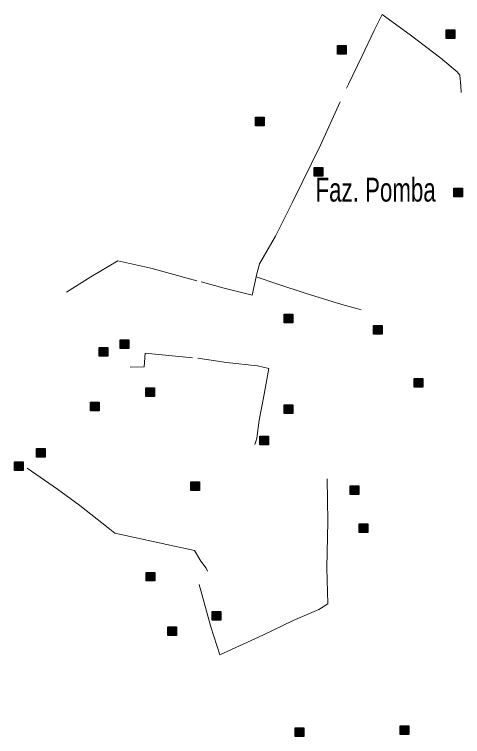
# Model space of a CAD drawing. Extents: x 445.6 to 500, y 8618.1 to 8673.4.
# Drawn here: x 450.664 to 453.675, y 8662.032 to 8666.886 of the extents above; entities that cross this region are included whole.
import ezdxf

# ---------------------------------------------------------------- set-up
doc = ezdxf.new("R2010")
doc.units = 0
doc.header["$LTSCALE"] = 0.064
doc.linetypes.add('DOT_DASHED', pattern=[7.7, 5, -1.2, 0.3, -1.2])
doc.layers.add('2', color=7, linetype='Continuous', lineweight=25)
doc.layers.add('22', color=7, linetype='DOT_DASHED', lineweight=13)
doc.layers.add('61', color=7, linetype='Continuous')

msp = doc.modelspace()

# ---------------------------------------------------------------- hatches: boundary and pattern name
at = {"layer": '2'}
for points in [[(453.5643, 8666.783), (453.6223, 8666.783), (453.6223, 8666.725), (453.5643, 8666.725)], [(452.8348, 8666.6766), (452.8928, 8666.6766), (452.8928, 8666.6186), (452.8348, 8666.6186)], [(452.2843, 8666.1955), (452.3423, 8666.1955), (452.3423, 8666.1375), (452.2843, 8666.1375)], [(452.678, 8665.8576), (452.736, 8665.8576), (452.736, 8665.7996), (452.678, 8665.7996)], [(453.6167, 8665.719), (453.6747, 8665.719), (453.6747, 8665.661), (453.6167, 8665.661)], [(452.4762, 8664.8717), (452.5342, 8664.8717), (452.5342, 8664.8137), (452.4762, 8664.8137)], [(453.0763, 8664.7941), (453.1343, 8664.7941), (453.1343, 8664.7361), (453.0763, 8664.7361)], [(451.3756, 8664.6985), (451.4336, 8664.6985), (451.4336, 8664.6405), (451.3756, 8664.6405)], [(451.2337, 8664.6477), (451.2917, 8664.6477), (451.2917, 8664.5897), (451.2337, 8664.5897)], [(453.3499, 8664.4384), (453.4079, 8664.4384), (453.4079, 8664.3804), (453.3499, 8664.3804)], [(451.5478, 8664.3769), (451.6058, 8664.3769), (451.6058, 8664.3189), (451.5478, 8664.3189)], [(451.1762, 8664.2792), (451.2342, 8664.2792), (451.2342, 8664.2212), (451.1762, 8664.2212)], [(452.4762, 8664.2619), (452.5342, 8664.2619), (452.5342, 8664.2039), (452.4762, 8664.2039)], [(452.3131, 8664.0514), (452.3711, 8664.0514), (452.3711, 8663.9934), (452.3131, 8663.9934)], [(450.8132, 8663.9672), (450.8712, 8663.9672), (450.8712, 8663.9092), (450.8132, 8663.9092)], [(450.6645, 8663.8791), (450.7225, 8663.8791), (450.7225, 8663.8211), (450.6645, 8663.8211)], [(451.8485, 8663.7436), (451.9065, 8663.7436), (451.9065, 8663.6856), (451.8485, 8663.6856)], [(452.9192, 8663.7165), (452.9772, 8663.7165), (452.9772, 8663.6585), (452.9192, 8663.6585)], [(452.98, 8663.4624), (453.038, 8663.4624), (453.038, 8663.4044), (452.98, 8663.4044)], [(451.5487, 8663.1358), (451.6067, 8663.1358), (451.6067, 8663.0778), (451.5487, 8663.0778)], [(451.9921, 8662.8724), (452.0501, 8662.8724), (452.0501, 8662.8144), (451.9921, 8662.8144)], [(451.6953, 8662.7697), (451.7533, 8662.7697), (451.7533, 8662.7117), (451.6953, 8662.7117)], [(452.5499, 8662.0899), (452.6079, 8662.0899), (452.6079, 8662.0319), (452.5499, 8662.0319)], [(453.2558, 8662.1034), (453.3138, 8662.1034), (453.3138, 8662.0454), (453.2558, 8662.0454)]]:
    msp.add_hatch(color=256, dxfattribs=at).paths.add_polyline_path(points)

# ---------------------------------------------------------------- linework, layer by layer
for points in [[(453.5643, 8666.783), (453.6223, 8666.783), (453.6223, 8666.725), (453.5643, 8666.725)], [(452.8348, 8666.6766), (452.8928, 8666.6766), (452.8928, 8666.6186), (452.8348, 8666.6186)], [(452.2843, 8666.1955), (452.3423, 8666.1955), (452.3423, 8666.1375), (452.2843, 8666.1375)], [(452.678, 8665.8576), (452.736, 8665.8576), (452.736, 8665.7996), (452.678, 8665.7996)], [(453.6167, 8665.719), (453.6747, 8665.719), (453.6747, 8665.661), (453.6167, 8665.661)], [(452.4762, 8664.8717), (452.5342, 8664.8717), (452.5342, 8664.8137), (452.4762, 8664.8137)], [(453.0763, 8664.7941), (453.1343, 8664.7941), (453.1343, 8664.7361), (453.0763, 8664.7361)], [(451.3756, 8664.6985), (451.4336, 8664.6985), (451.4336, 8664.6405), (451.3756, 8664.6405)], [(451.2337, 8664.6477), (451.2917, 8664.6477), (451.2917, 8664.5897), (451.2337, 8664.5897)], [(453.3499, 8664.4384), (453.4079, 8664.4384), (453.4079, 8664.3804), (453.3499, 8664.3804)], [(451.5478, 8664.3769), (451.6058, 8664.3769), (451.6058, 8664.3189), (451.5478, 8664.3189)], [(451.1762, 8664.2792), (451.2342, 8664.2792), (451.2342, 8664.2212), (451.1762, 8664.2212)], [(452.4762, 8664.2619), (452.5342, 8664.2619), (452.5342, 8664.2039), (452.4762, 8664.2039)], [(452.3131, 8664.0514), (452.3711, 8664.0514), (452.3711, 8663.9934), (452.3131, 8663.9934)], [(450.8132, 8663.9672), (450.8712, 8663.9672), (450.8712, 8663.9092), (450.8132, 8663.9092)], [(450.6645, 8663.8791), (450.7225, 8663.8791), (450.7225, 8663.8211), (450.6645, 8663.8211)], [(451.8485, 8663.7436), (451.9065, 8663.7436), (451.9065, 8663.6856), (451.8485, 8663.6856)], [(452.9192, 8663.7165), (452.9772, 8663.7165), (452.9772, 8663.6585), (452.9192, 8663.6585)], [(452.98, 8663.4624), (453.038, 8663.4624), (453.038, 8663.4044), (452.98, 8663.4044)], [(451.5487, 8663.1358), (451.6067, 8663.1358), (451.6067, 8663.0778), (451.5487, 8663.0778)], [(451.9921, 8662.8724), (452.0501, 8662.8724), (452.0501, 8662.8144), (451.9921, 8662.8144)], [(451.6953, 8662.7697), (451.7533, 8662.7697), (451.7533, 8662.7117), (451.6953, 8662.7117)], [(452.5499, 8662.0899), (452.6079, 8662.0899), (452.6079, 8662.0319), (452.5499, 8662.0319)], [(453.2558, 8662.1034), (453.3138, 8662.1034), (453.3138, 8662.0454), (453.2558, 8662.0454)]]:
    msp.add_lwpolyline(points, close=True, dxfattribs=at)
at = {"layer": '22'}
for points in [[(452.2874, 8665.1214), (452.292, 8665.1427), (452.3108, 8665.2094), (452.4185, 8665.3959), (452.5333, 8665.6232), (452.598, 8665.7566), (452.7196, 8666.0083), (452.9077, 8666.4179), (452.9975, 8666.6035), (453.0814, 8666.7778), (453.1336, 8666.8862), (453.3236, 8666.7486), (453.5282, 8666.5922), (453.6395, 8666.4998), (453.6562, 8666.4789), (453.6625, 8666.4059), (453.6655, 8666.3615)], [(451.0139, 8665.0192), (451.1769, 8665.1218), (451.3586, 8665.2302), (451.58, 8665.1802), (451.9182, 8665.0884), (452.0728, 8665.0467), (452.2607, 8664.9988), (452.2874, 8665.1214)], [(452.2874, 8665.1214), (452.4349, 8665.0736), (452.617, 8665.0119), (452.8643, 8664.9368), (452.9612, 8664.9101), (452.9928, 8664.9008)], [(451.4417, 8664.5146), (451.5364, 8664.5164), (451.5431, 8664.6082), (451.8956, 8664.5748), (452.0894, 8664.5465), (452.2975, 8664.5231), (452.3744, 8664.5064), (452.3376, 8664.3079), (452.3076, 8664.1594), (452.2926, 8664.0382), (452.2859, 8664.0148), (452.2794, 8663.9948)], [(450.7498, 8663.8367), (450.954, 8663.6944), (451.1026, 8663.5844), (451.2943, 8663.436), (451.3399, 8663.4001), (451.637, 8663.3331), (451.8743, 8663.2828), (451.9161, 8663.212), (451.9521, 8663.1642), (451.9623, 8663.1438)], [(451.9048, 8663.0542), (451.983, 8662.77), (452.0434, 8662.582), (452.333, 8662.7145), (452.5358, 8662.811), (452.7095, 8662.8857), (452.7699, 8662.9242), (452.7626, 8663.1653), (452.7704, 8663.4776), (452.7659, 8663.7634)]]:
    msp.add_lwpolyline(points, dxfattribs=at)

# ---------------------------------------------------------------- texts
at = {"layer": '61', "width": 0.7}
msp.add_text('Faz. Pomba', height=0.16, dxfattribs=at).set_placement((452.687, 8665.6282))

doc.saveas('drawing.dxf')
